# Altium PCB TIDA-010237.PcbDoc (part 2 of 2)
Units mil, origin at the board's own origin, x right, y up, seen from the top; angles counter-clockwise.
Board outline 2362.2 x 3346.46 mil, 4 copper layers (Top Layer, GND, Power, Bottom Layer), stack 61.6 mil thick; 143 components, 71 nets, 356 pads, 186 vias.
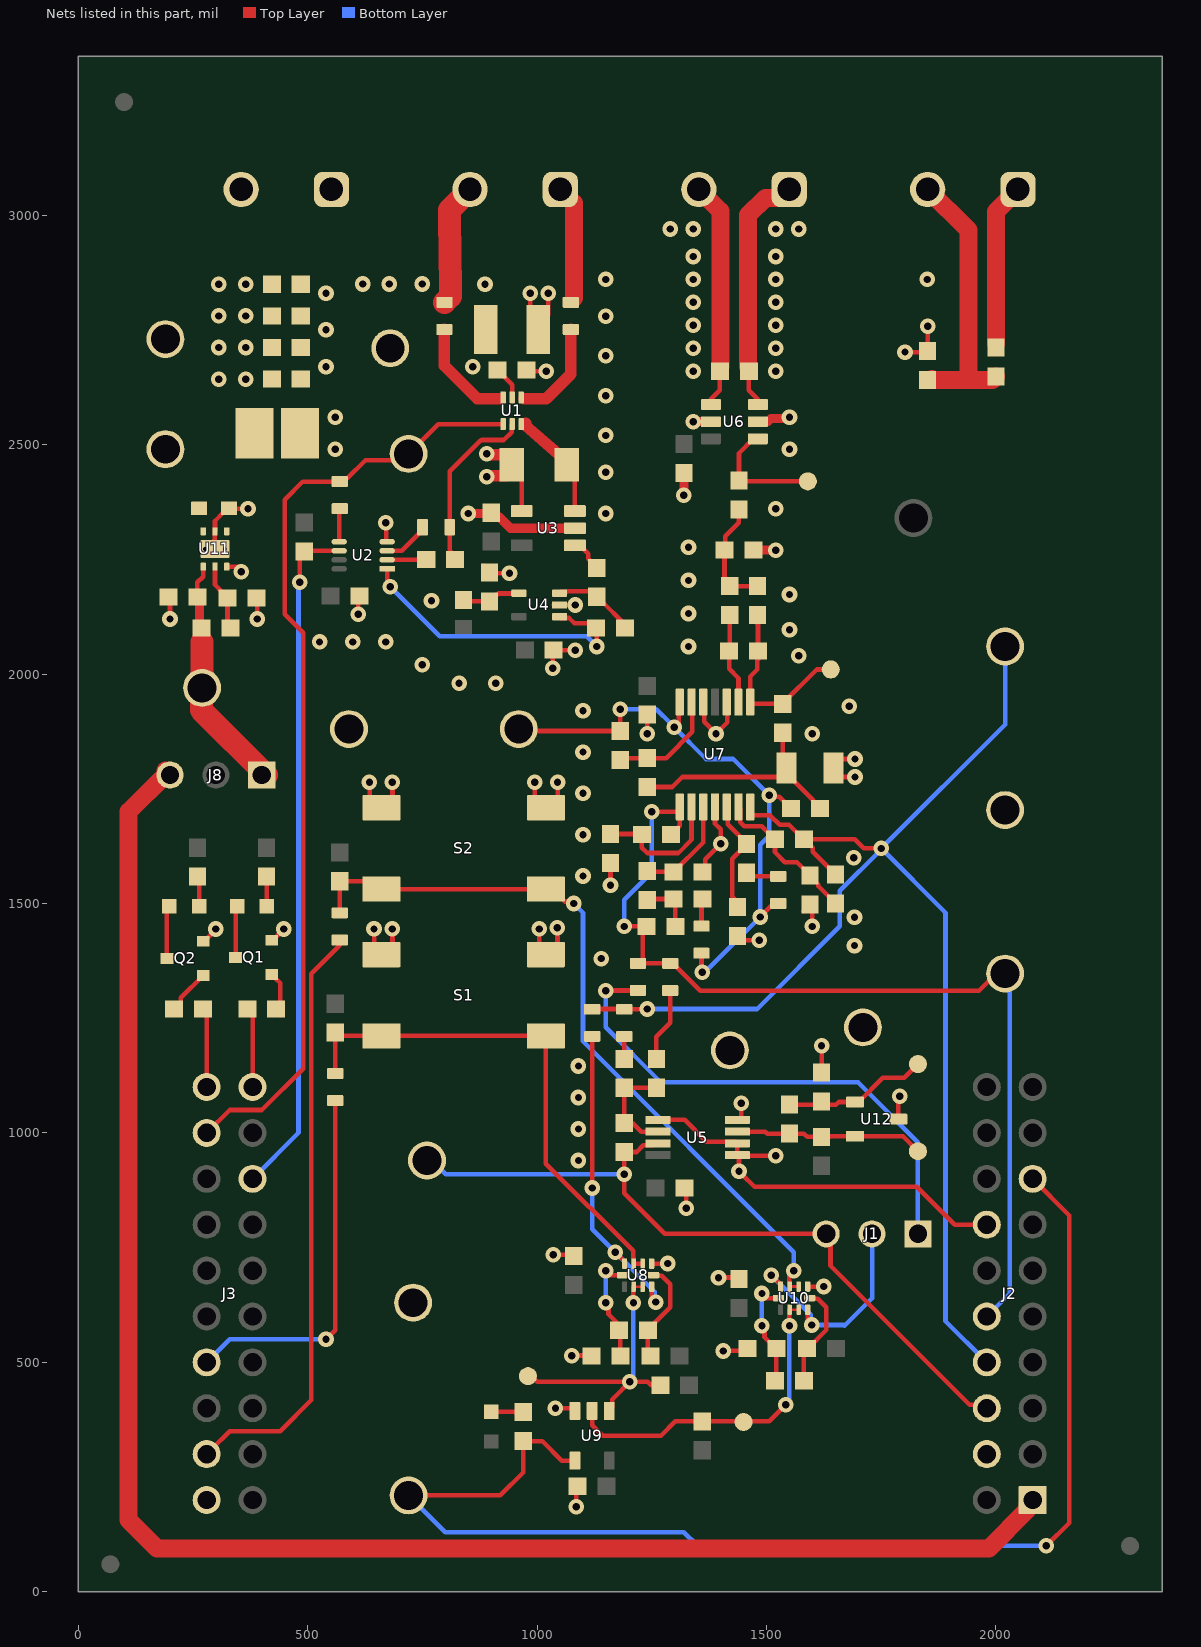
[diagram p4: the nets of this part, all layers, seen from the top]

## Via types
v1: diameter 34, hole 16, Top Layer to Bottom Layer, tented both sides, 184 vias
v2: diameter 19.68, hole 7.87, Top Layer to Bottom Layer, 2 vias

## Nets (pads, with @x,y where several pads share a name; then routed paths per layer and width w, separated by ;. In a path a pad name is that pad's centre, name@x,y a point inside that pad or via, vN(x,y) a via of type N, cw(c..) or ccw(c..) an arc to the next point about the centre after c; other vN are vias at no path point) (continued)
3V3-Launchpad: J2.1 J8.3 | length 3707.6
  Top Layer w39.37: J8.3@190,1790 190,1780 110,1700 110,156.81 172.13,94.68 1984.92,94.68 2069.17,178.94 2069.17,189.17 2076.85,196.85 J2.1@2077.24,196.85
3V3-LDO: C22.1 J8.1 R54.2 TP22.1 U11.1 | length 491.7
  Top Layer w10: C22.1@259.77,2167.98 259.77,2199.77 272.44,2212.44 U11.1@272.44,2234.21
  Top Layer w20: C22.1@259.77,2167.98 264.14,2163.62 264.14,2104.36 R54.2@268.5,2100
  Top Layer w50: 270,2070 268.5,1921.5 J8.1@410,1780
+12V: C1.1 C2.1 C21.2 C23.1 C24.1 C25.1 C26.1 C27.1 J4.2 TP12.1 U1.5 U11.4 U11.6 | length 63.2
  Top Layer w10: C2.1@914.17,2662.36 915.16,2662.36 928.86,2648.66 928.86,2647.68 945.67,2630.87 U1.5@945.67,2612.76
  other v1: 305.91,2642.68 364.96,2642.68 860,2670 305.91,2711.57 364.96,2711.57 305.91,2780.47 364.96,2780.47 305.91,2849.37 364.96,2849.37 886.61,2849.37
AC_clr: R34.2 R36.2 S1.1 S1.2 U8.2 U8.3 | length 1145.4
  Top Layer w10: R36.2@560,1129.53 R34.2@560,1218.5 ; R34.2@560.73,1218.5 567.81,1211.42 S1.2@660.87,1211.42 S1.1@1019.13,1211.42 1019.13,933.11 1209.25,743 1209.25,727.32 1210.16,726.42 U8.3@1210.16,715.1 U8.2@1229.84,715.1
AC_Sense+: J5.1 R15.2 U6.3 | length 523.3
  Top Layer w10: R15.2@1461.5,2660 1461.5,2618.9 1481.18,2599.21 U6.3@1481.18,2587.4
  Top Layer w39.37: R15.2@1460,2670 1460,3000 1497.55,3037.55 1530.83,3037.55 J5.1@1549.34,3056.06
AC_Sense-: J5.2 R15.1 U6.4 | length 486.5
  Top Layer w10: U6.4@1378.82,2587.4 1378.82,2599.21 1398.5,2618.9 R15.1@1398.5,2660
  Top Layer w39.37: J5.2@1352.49,3056.06 1400,3008.56 R15.1@1400,2670
AC_SENSING: C11.2 J2.24 R29.2 R32.2 R33.2 TP6.1 U7.14 | length 3025.4
  Top Layer w10: R29.2@1120,1270 1189.53,1270 R33.2@1190,1269.53 1239.53,1269.53 v1(1240,1270) ; U7.14@1464.57,1710.63 1464.57,1696.49 1468.43,1692.63 1507.37,1692.63 1528.43,1671.57 1548.94,1671.57 1580.51,1640 R32.2@1581.5,1640 R32.2@1582.48,1640 ; C11.2@1650,1562.99 1650,1563.98 1601.18,1612.8 1601.18,1621.3 R32.2@1582.48,1640 ; v1(1750,1620) 1712.25,1620 1692.25,1640 R32.2@1582.48,1640
  Bottom Layer w10: v1(1240,1270) 1479.75,1270 1660,1450.25 1660,1527.75 1750,1617.75 v1(1750,1620) ; J2.24@1980,500 1890,590 1890,1480 v1(1750,1620) ; TP6.1@2020,2060 2020,1890 v1(1750,1620)
AC_windowComp_CLR: J3.17 R36.1 | length 805.3
  Top Layer w10: v1(540,550) 560,570 R36.1@560,1070.47
  Bottom Layer w10: J3.17@280,510 290,510 330,550 v1(540,550)
COMPOSITE_SENSING: J1.3 J2.23 R40.2 TP8.1 U5.7 | length 1646.8
  Top Layer w10: U5.7@1260,980 1253.35,973.35 1231.64,973.35 1216.79,958.5 R40.2@1190,958.5 v1(1190,910) 1190,868.56 1278.56,780 J1.3@1630,780 1639.39,770.61 1639.39,710.61 1942.82,407.18 1972.82,407.18 J2.23@1980,400
  Bottom Layer w10: TP8.1@736.8,923.2 788.19,923.2 801.39,910 v1(1190,910)
DC_clr: R42.2 R46.2 S2.1 S2.2 U10.2 U10.3 | length 1649.3
  Top Layer w6: U10.3@1550.16,665.1 U10.2@1569.84,665.1
  Top Layer w10: R46.2@570,1479.53 R42.2@570,1548.5 S2.2@660.87,1548.5 ; S2.2@660.87,1531.42 S2.1@1019.13,1531.42 1032.91,1531.42 1059.91,1504.42 1075.58,1504.42 v1(1080,1500) ; U10.3@1550.16,665.1 1550.16,676.42 1550,676.57 1550,690 1559.65,699.65 v1(1559.65,700)
  Bottom Layer w10: v1(1080,1500) 1100,1480 1100,1200 1559.65,740.35 v1(1559.65,700)
DC_SENSING: C16.2 J2.25 R41.1 R47.2 R50.2 TP10.1 U7.8 | length 2172.1
  Top Layer w10: v1(1190,1450) C16.2@1238.5,1450 1230,1441.5 R50.2@1230,1369.53 ; R50.2@1220,1369.53 R50.2@1230,1369.53 ; v1(1250,1700) 1309.13,1700 1311.02,1701.89 1311.02,1714.57 1311.02,1669.56 1306.18,1664.72 1306.18,1663.7 1292.48,1650 R47.2@1290.51,1650 ; TP10.1@2020,1350 2003.17,1350 1963.17,1310 1355.43,1310 1295.91,1369.53 R41.1@1290,1369.53 R50.2@1230,1369.53
  Bottom Layer w10: v1(1190,1450) 1190,1507.75 1250,1567.75 v1(1250,1700) ; J2.25@1980,600 2030,650 2030,1340 TP10.1@2020,1350
DC_windowComp_CLR: J3.19 R46.1 | length 1300.9
  Top Layer w10: J3.19@280,310 290,310 330,350 440,350 507.87,417.87 507.87,1346.54 570,1408.66 R46.1@570,1420.47
FluxGate+: J6.2 R1.1 | length 269.8
  Top Layer w50: R1.1@798.03,2810 811,2823.27 811,2843.59 811,2843.88 810.99,2844.07 ccw(c761,2843.59) 810.99,2844.27 809.3,2990.56 809.3,3011.56 J6.2@853.81,3056.06
FluxGate-: J6.1 R2.1 | length 248.2
  Top Layer w39.37: J6.1@1050.66,3056.06 1080,3026.72 R2.1@1080,2820
GND: C1.2 C2.2 C3.2 C4.2 C5.2 C7.2 C8.2 C10.2 C12.2 C13.2 C14.2 C17.2 C18.2 C19.2 C21.1 C22.2 C23.2 C24.2 C25.2 C26.2 C27.2 J2.22 J3.20 J4.1 Q1.2 Q2.2 R3.1 R9.1 R19.1 R35.2 R53.2 R55.1 R57.1 S1.3 S1.4 S2.3 S2.4 TP13.1 TP14.1 TP15.1 TP16.1 TP17.1 TP19.1 U2.4 U3.2 U3.4 U4.2 U5.4 U6.2 U7.11 U8.1 U9.3 U10.1 U11.3 U11.5 U11.7@298.03,2272.6 U12.3 | length 2515.3
  Top Layer w10: v1(200,2120) C22.2@200,2161.36 ; Q2.2@272.36,1424.65 280.86,1424.65 299.92,1443.7 v1(299.92,1444.33) ; 296.06,2292.28 297.13,2293.35 297.13,2310.08 U11.5@298.03,2310.98 298.03,2333.62 315.59,2351.18 316.06,2351.18 325.59,2360.71 C21.1@325.59,2361.18 ; U11.3@323.51,2234.1 323.88,2233.72 354.63,2233.72 v1@355.12,2233.23 ; C21.1@326.88,2361.18 327.47,2360.59 369.41,2360.59 v1(370,2360) ; R55.1@388.3,2166.03 390,2164.32 v1(390,2120) ; Q1.2@425.49,1422.26 Q1.2@427.87,1424.65 ; Q1.2@428.5,1424.65 v1@447.56,1443.7 ; v1(610,2130) C5.2@610,2167.24 ; S2.4@634.9,1729.53 v1@634.9,1764.29 ; S1.4@644.9,1409.53 v1@644.9,1444.29 ; v1(670,2330) 671.53,2328.47 671.53,2289.12 672.31,2288.35 U2.4@673.07,2288.35 ; S1.4@684.9,1409.53 v1@684.9,1444.29 ; S2.4@684.9,1729.53 v1@684.9,1764.29 ; R9.1@883.17,2235.69 898.86,2220 v1(940,2220) ; R3.1@944.64,2445.83 966.34,2424.13 966.34,2360.19 U3.4@955.51,2349.37 ; C2.2@978.14,2662.36 980.5,2660 v1(1020,2660) ; C1.2@985.04,2782.44 v1(985.04,2829.69) ; S2.3@994.9,1729.53 v1@994.9,1764.29 ; C1.2@1002.76,2750.94 C1.2@1017.84,2735.86 ; S1.3@1004.9,1409.53 v1@1004.9,1444.29 ; C1.2@1024.41,2782.44 v1(1024.41,2829.69) ; v1(1034.25,2012.76) C4.2@1034.25,2060 ; v1(1035.47,734.67) 1035.71,734.9 C14.2@1070.47,734.9 ; C4.2@1036.22,2052.13 v1(1083.46,2052.13) ; U4.2@1036.22,2150.55 v1(1083.46,2150.55) ; v1(1040,400) 1084.43,400 U9.3@1084.9,399.53 ; S1.3@1044.49,1412.5 v1@1044.49,1447.26 ; S2.3@1044.9,1729.53 v1@1044.9,1764.29 ; v1(1075.47,514.67) 1075.71,514.9 R35.2@1110.47,514.9 ; C18.2@1085.1,220.47 1085.1,185.71 v1(1085.33,185.47) ; v1(1240,1870) 1240,1903.39 1250,1913.39 C10.2@1250,1921.26 ; U8.1@1249.53,715.1 1284.29,715.1 v1(1284.53,715.33) ; C7.2@1325.1,870.47 1325.1,835.71 v1(1325.33,835.47) ; C19.2@1360.24,1568.9 1366.74,1575.4 1366.74,1596.74 v1(1400,1630) 1399.93,1630.07 1399.93,1662 1387.8,1674.13 U7.11@1387.8,1714.57 ; v1(1395.47,684.67) 1395.71,684.9 C17.2@1430.47,684.9 ; v1(1405.47,524.67) 1405.71,524.9 R53.2@1440.47,524.9 ; v1@1440,1060 1441.18,1061.18 1444.9,1061.18 U5.4@1444.9,1029.53 ; U10.1@1589.53,665.1 1624.29,665.1 v1(1624.53,665.33) ; R19.1@1620,1131.5 v1(1620,1190) ; C13.2@1653.54,1783.46 1661.42,1775.59 v1(1692.91,1775.59) ; C13.2@1661.42,1814.96 v1(1692.91,1814.96) ; U12.3@1787.24,1030 1787.24,1067.24 1790,1070 v1(1790,1080) ; v1(1801.81,2701.73) R57.1@1849.05,2701.73 ; R57.1@1851.73,2710.94 v1(1851.73,2758.19)
  Top Layer w19.68: v1(1320,2390) C8.2@1320,2438.5 ; C12.2@1471.5,2270 v1(1520,2270) ; U6.2@1481.18,2550 1502.83,2550 1510.1,2557.26 1547.26,2557.26 v1(1550,2560)
  Top Layer w20: v1@860,2350 C3.2@900,2350 ; C3.2@900,2351.5 900,2350.51 908.7,2341.81 918.19,2341.81 942.13,2317.87 U3.2@1082.48,2317.87
  Top Layer w25: v1(890,2430) 891.72,2431.72 931.72,2431.72 R3.1@938.28,2438.28 ; v1@891.72,2478.28 R3.1@938.28,2478.28 ; R3.1@938.28,2458.28 R3.1@940,2460
  other v1: 1090.12,940 1090.12,1008.59 1444.67,1064.53 1090.12,1077.19 1090.12,1145.78 1140,1380 1691.81,1408.33 447.56,1444.33 644.67,1444.53 684.67,1444.53 1004.67,1444.53 1044.25,1447.5 1691.81,1470 1100,1560 1690,1600 1100,1650 1100,1740 634.67,1764.53 684.67,1764.53 994.67,1764.53 1044.67,1764.53 1100,1830 1600,1870 1100,1920 1680,1930 830,1980 910,1980 750,2020 1570,2040 1330,2060 525.96,2070 597.98,2070 670,2070 1550,2096.67 1330,2132.02 770,2160 1550,2173.33 1330,2204.04 355.12,2223.23 1330,2276.06 850,2350 1150,2350 1520,2360 1150,2440 890,2480 560,2490 1550,2490 1150,2520 560,2560 1150,2606.67 1340,2660 1520,2660 540,2670 1150,2693.33 1340,2710 1520,2710 540,2750 1340,2760 1520,2760 1150,2780 1340,2810 1520,2810 540,2830 620,2850 677.98,2850 750,2850 1150,2860 1340,2860 1520,2860 1850,2860 1340,2910 1520,2910 1290,2970 1340,2970 1520,2970 1570,2970
  other v2: 276.38,2272.6 319.68,2272.6
GREEN_LED: J3.11 R60.2 | length 170
  Top Layer w10: J3.11@280,1100 R60.2@280,1270
I_fault: C9.1 R13.2 R28.2 R48.2 TP3.1 U7.7 | length 1314.5
  Top Layer w10: TP3.1@960,1880 964.02,1875.98 C9.1@1181.1,1875.98 v1(1181.1,1923.23) ; v1@1309.13,1893.78 U7.7@1309.13,1933.15 ; R48.2@1358.27,1391.73 1358.27,1351.73 v1(1360,1350) ; v1@1486.22,1471.1 R28.2@1520.36,1505.23 ; v1(1505.91,1736.22) 1509.67,1732.45 1527.39,1732.45 1538.46,1721.38 1538.46,1720.39 1552.17,1706.69 R13.2@1553.15,1706.69
  Bottom Layer w10: v1(1181.1,1923.23) 1259.84,1923.23 1293.07,1890 v1@1300,1890 ; v1@1296.54,1886.54 v1(1299.21,1883.86) 1368.11,1814.96 1427.17,1814.96 v1(1505.91,1736.22) 1505.91,1647.64 1486.22,1627.95 v1(1486.22,1470.47) 1365.75,1350 v1(1360,1350)
NetC6_1: C6.1 R12.2 R21.1 TP2.1 U7.1 | length 408.2
  Top Layer w10: R12.2@1480,2128.5 1480,2108.82 1481.5,2107.32 C6.1@1481.5,2050 1481.5,2031.3 1480,2029.8 1480,2010 1464.57,1994.57 U7.1@1464.57,1938.98 1464.57,1935.04 1471.46,1935.04 R21.1@1535.43,1935.04 1535.43,1936.02 1609.41,2010 TP2.1@1640,2010
NetC6_2: C6.2 R16.2 U7.2 | length 198.6
  Top Layer w10: R16.2@1420,2128.5 1420,2051.5 C6.2@1418.5,2050 1418.5,2011.5 1438.98,1991.02 U7.2@1438.98,1938.98
NetC9_2: C9.2 R22.2 U7.6 | length 241
  Top Layer w10: C9.2@1181.1,1814.96 1183.07,1816.93 1281.5,1816.93 1338.58,1874.02 U7.6@1338.58,1933.07
NetC11_1: C11.1 R31.2 R32.1 U7.13 | length 336.3
  Top Layer w10: U7.13@1438.98,1710.63 1442.83,1706.77 1442.83,1676.91 1451.52,1668.23 1489.29,1668.23 1503.82,1653.7 1517.52,1640 R32.1@1518.5,1640 1518.5,1611.5 1540,1590 1566.5,1590 1594.49,1562.01 R31.2@1594.49,1561.02 1594.49,1560.04 1613.19,1541.34 1613.19,1537.8 1650,1500.98 C11.1@1650,1500
NetC12_1: C12.1 R12.1 R16.1 R18.2 | length 244.6
  Top Layer w10: C12.1@1408.5,2270 1408.5,2212.68 1410,2211.18 1410,2191.5 R12.1@1480,2191.5 ; C12.1@1410,2275.44 1410,2300 1439.68,2329.68 1439.68,2358.18 R18.2@1440,2358.5
NetC13_1: C13.1 R13.1 R21.2 R22.1 | length 455
  Top Layer w10: R22.1@1240.16,1753.94 1294.97,1753.94 1316.62,1775.59 C13.1@1525.59,1775.59 ; C13.1@1535.43,1795.28 R21.2@1535.43,1872.05 ; C13.1@1555.12,1771.59 1601.46,1725.25 1601.46,1714.98 R13.1@1607.12,1709.31
NetC15_1: C15.1 R27.1 U7.12 | length 264.4
  Top Layer w10: U7.12@1413.39,1714.57 1415.28,1712.68 1415.28,1672.32 1456.69,1630.91 1456.69,1628.94 1425.12,1597.36 1425.12,1514.84 1446.85,1493.11 R27.1@1446.85,1492.13 ; R27.1@1437.01,1490.16 R27.1@1437.01,1492.13
NetC15_2: C15.2 R28.1 | length 72.2
  Top Layer w10: C15.2@1456.69,1566.93 1464.57,1559.06 R28.1@1525.59,1559.06
NetC16_1: C16.1 R45.1 R49.2 | length 115.8
  Top Layer w10: R45.1@1240,1510 1240.16,1509.84 R49.2@1297.24,1509.84 ; C16.1@1301.5,1450 R49.2@1301.5,1508.5
NetC19_1: C19.1 R45.2 U7.10 | length 230.2
  Top Layer w10: R45.2@1240.16,1568.9 C19.1@1297.24,1568.9 1298.23,1568.9 1362.2,1632.87 U7.10@1362.2,1714.57
NetD1_1: D1.1 R38.2 | length 70.4
  Top Layer w10: D1.1@900,392.48 950.31,392.48 951.3,391.5 R38.2@970,391.5
NetD4_1: D4.1 Q2.3 | length 115.2
  Top Layer w10: Q2.3@193.39,1380.48 193.39,1488.39 D4.1@198.54,1493.54
NetD4_2: D4.2 R59.1 | length 66.4
  Top Layer w10: R59.1@260,1558.5 263.5,1555 D4.2@263.5,1493.54
NetD5_1: D5.1 Q1.3 | length 112.4
  Top Layer w10: Q1.3@342.89,1382.48 342.89,1490.25 D5.1@346.18,1493.54
NetD5_2: D5.2 R58.1 | length 80
  Top Layer w10: R58.1@408.19,1572.28 411.14,1569.33 D5.2@411.14,1493.54
NetJ1_1: J1.1 R50.1 | length 1133.7
  Top Layer w10: v1(1150,1310) 1150.47,1310.47 R50.1@1220,1310.47
  Bottom Layer w10: v1(1150,1310) 1150,1230 1270,1110 1700,1110 1830,980 J1.1@1830,780
NetJ1_2: J1.2 U10.4 U10.9 | length 512.8
  Top Layer w10: v1(1510,690) 1510.98,690 1530.47,670.51 U10.4@1530.47,665.1 ; U10.9@1589.53,614.9 1589.53,603.58 1590,603.11 1590,590 v1(1598.62,581.38)
  Bottom Layer w10: v1(1510,690) 1595.99,604.01 1595.99,584.01 v1(1598.62,581.38) 1670,581.38 ; 1670,580 1730,640 J1.2@1730,780
NetQ1_1: Q1.1 R61.2 | length 97.1
  Top Layer w10: Q1.1@421.63,1345.08 423.6,1345.08 430.41,1338.27 430.41,1336.3 440,1326.71 R61.2@440,1256.79
NetQ2_1: Q2.1 R60.1 | length 100.8
  Top Layer w10: R60.1@220,1263.86 223.7,1267.57 223.7,1294.65 Q2.1@272.13,1343.08
NetR1_2: R1.2 U1.6 | length 230.1
  Top Layer w25: R1.2@798.03,2750.94 798.03,2671.97 870,2600 919.39,2600
NetR2_2: R2.2 U1.4 | length 221.2
  Top Layer w25: 971.95,2600 1020,2600 1073.62,2653.62 R2.2@1073.62,2750.94
NetR5_2: R5.2 U2.5 | length 71.8
  Top Layer w10: R5.2@561.85,2357.24 568.66,2350.43 U2.5@568.66,2288.35
NetR6_2: R6.2 U2.3 | length 99.3
  Top Layer w10: U2.3@673.07,2268.66 673.39,2268.98 705.36,2268.98 748.82,2312.44 R6.2@748.82,2317.87
NetR7_2: R7.2 U2.2 | length 65.9
  Top Layer w10: U2.2@673.07,2248.98 R7.2@738.98,2248.98
NetR8_1: R8.1 U3.1 | length 75
  Top Layer w10: U3.1@1082.48,2280.47 1093.31,2280.47 1111.3,2262.48 1111.3,2251.18 1130,2232.48 R8.1@1130,2231.5
NetR8_2: R8.2 R11.1 U4.3 | length 186.1
  Top Layer w10: U4.3@1049.02,2176.14 1051.89,2179.02 1065.2,2179.02 1066.61,2180.43 1099.38,2180.43 1099.47,2180.33 1118.17,2180.33 R8.2@1130,2168.5 1130,2167.52 1143.7,2153.82 1145.87,2153.82 1184.45,2115.24 1184.45,2114.25 1198.15,2100.55 R11.1@1199.13,2100.55
NetR11_2: R11.2 U2.1 U4.1 | length 663
  Top Layer w10: U2.1@673.07,2229.29 673.07,2203.27 679.92,2196.42 v1(679.92,2189.92) ; U4.1@1049.02,2124.96 1051.89,2122.09 1069.68,2122.09 1081.44,2110.32 1119.68,2110.32 R11.2@1120,2110 ; R11.2@1128.5,2099.06 1130,2097.56 v1(1130,2060)
  Bottom Layer w10: v1(679.92,2189.92) 787.84,2082 1108,2082 v1(1130,2060)
NetR14_2: R14.2 R17.2 TP20.1 U5.3 U12.2 | length 412
  Top Layer w10: U5.3@1436.61,1002.8 1497.2,1002.8 1501.5,998.5 1581.5,998.5 1588.5,991.5 1638.7,991.5 1639.8,992.6 U12.2@1692.76,992.6 1797.4,992.6 TP20.1@1830,960
NetR17_1: R17.1 R19.2 TP21.1 U12.1 | length 316.7
  Top Layer w10: R17.1@1550,1061.5 1651.5,1061.5 1657.4,1067.4 U12.1@1692.76,1067.4 1700.63,1067.4 1753.23,1120 1800,1120 TP21.1@1830,1150
NetR18_1: R18.1 TP5.1 U6.1 | length 258.1
  Top Layer w10: R18.1@1440,2421.5 1440,2481.26 1471.34,2512.6 U6.1@1481.18,2512.6 ; R18.1@1445.86,2420 TP5.1@1590,2420
NetR25_2: R25.2 TP7.1 U8.7 U8.8 U9.1 | length 609.3
  Top Layer w6: U8.7@1210.16,664.9 U8.8@1229.84,664.9
  Top Layer w10: TP7.1@980,470 987.92,470 1000.54,457.38 1197.38,457.38 v1@1200,460 ; U9.1@1157.4,394.13 1163.92,400.65 1163.92,419.15 1168.62,423.85 v1(1202.15,457.38) ; v1@1202.62,457.38 1241.44,457.38 1248.82,450 R25.2@1268.5,450 ; v1(1210,630) 1210,653.43 1210.16,653.58 U8.7@1210.16,664.9
  Bottom Layer w10: v1(1202.15,457.38) 1200,459.53 1200,460 1210,470 v1(1210,630)
NetR26_2: R26.2 R30.2 U8.10 | length 225.1
  Top Layer w10: R26.2@1241.5,510 1241.5,572.99 1248.5,580 1249.49,580 1290,620.51 1290,670 1271.6,688.4 1261.26,688.4 1259.66,690 U8.10@1253.86,690
NetR29_1: R29.1 U8.4 U8.9 | length 707.8
  Top Layer w10: v1(1120,880) R29.1@1120,1210.47 ; v1(1170,740) 1170.98,740 1190.47,720.51 U8.4@1190.47,715.1 ; U8.9@1249.53,664.9 1249.53,653.58 1250,653.11 1250,640 v1(1258.62,631.38)
  Bottom Layer w10: v1(1120,880) 1120,790 v1(1170,740) 1255.99,654.01 1255.99,634.01 v1(1258.62,631.38)
NetR30_1: R30.1 R35.1 U8.5 | length 245.1
  Top Layer w10: v1(1150,630) 1155.6,624.4 1155.6,604.92 1180.51,580 1181.5,580 1181.5,512.99 R35.1@1178.5,510 ; v1(1150,700) 1160,690 U8.5@1186.14,690
  Bottom Layer w10: v1(1150,630) v1(1150,700)
NetR33_1: R33.1 R37.1 | length 49
  Top Layer w10: R37.1@1190,1161.5 R33.1@1190,1210.47
NetR37_2: R37.2 R39.2 R40.1 U5.6 | length 228.1
  Top Layer w10: R39.2@1260,1098.5 R37.2@1190,1098.5 R40.1@1190,1021.5 1208.7,1021.5 1227.4,1002.8 U5.6@1263.39,1002.8
NetR39_1: R39.1 R41.2 | length 161.4
  Top Layer w10: R39.1@1260,1161.5 1260,1210 1290,1240 R41.2@1290,1310.47
NetR43_2: R43.2 TP11.1 U9.2 U10.7 U10.8 | length 722.8
  Top Layer w6: U10.7@1550.16,614.9 U10.8@1569.84,614.9
  Top Layer w10: U9.2@1120,394.13 1120,363.33 1143.33,340 1270,340 1301.5,371.5 R43.2@1360,371.5 1460,371.5 1506.27,371.5 v1(1542.15,407.38) ; v1(1550,580) 1550,603.43 1550.16,603.58 U10.7@1550.16,614.9
  Bottom Layer w10: v1(1542.15,407.38) 1540,409.53 1540,410 1550,420 v1(1550,580)
NetR44_2: R44.2 R51.2 U10.10 | length 225.1
  Top Layer w10: R51.2@1581.5,460 1581.5,522.99 R44.2@1588.5,530 1589.49,530 1630,570.51 1630,620 1611.6,638.4 1601.26,638.4 1599.66,640 U10.10@1593.86,640
NetR47_1: R47.1 R52.2 U7.9 | length 298.4
  Top Layer w10: R52.2@1160,1651.5 1227.01,1651.5 R47.1@1228.5,1650 1228.5,1621.5 1240,1610 1308.09,1610 1336.61,1638.53 U7.9@1336.61,1714.57
NetR48_1: R48.1 R49.1 | length 59.9
  Top Layer w10: R48.1@1358.27,1450.79 1358.27,1507.87 R49.1@1360.24,1509.84
NetR51_1: R51.1 R53.1 U10.5 | length 245.1
  Top Layer w10: v1(1490,580) 1495.6,574.4 1495.6,554.92 1520.51,530 R53.1@1521.5,530 1521.5,462.99 R51.1@1518.5,460 ; v1(1490,650) 1500,640 U10.5@1526.14,640
  Bottom Layer w10: v1(1490,580) v1(1490,650)
NetR54_1: R54.1 R55.2 U11.2 | length 108.9
  Top Layer w10: 298.03,2224.21 298.03,2194.32 R55.2@313.78,2178.57 ; R54.1@325.3,2109.28 R55.2@325.3,2166.03
nFault: J2.8 R38.1 TP9.1 U9.4 | length 2802.1
  Top Layer w10: TP9.1@695.92,210 920,210 970,260 R38.1@970,328.5 1011.5,328.5 1054.13,285.87 U9.4@1082.6,285.87 ; J2.8@2080,900 2160,820 2160,150 v1(2110,100)
  Bottom Layer w10: TP9.1@706.47,223.53 800,130 1320,130 1350,100 v1(2110,100)
Pulse+: J3.12 R5.1 TP1.1 U1.1 | length 2096.6
  Top Layer w10: J3.12@280,1000 330,1050 400,1050 490,1140 490,2090 450,2130 450,2380 489.53,2419.53 R5.1@570,2419.53 576.81,2426.34 586.34,2426.34 626.09,2466.09 706.09,2466.09 784.65,2544.65 U1.1@925.98,2544.65
  Bottom Layer w10: TP1.1@720,2489.84 TP1.1@739.68,2470.16
Pulse-: R6.1 R7.1 U1.2 | length 393.1
  Top Layer w10: R6.1@809.53,2320 809.53,2441.78 877.63,2509.87 879.87,2509.87 880,2510 927.5,2510 944.76,2527.27 944.76,2534.65 944.76,2543.74 945.67,2534.65 U1.2@945.67,2544.49 ; R6.1@810,2320 810,2268.5 R7.1@819.69,2258.82
RED_LED: J3.31 R61.1 | length 153.8
  Top Layer w10: J3.31@380,1100 R61.1@380,1253.81
RESET_n: J3.33 R10.2 U2.6 | length 1503.2
  Top Layer w10: v1(483.07,2199.76) 483.07,2257.17 494.57,2268.66 U2.6@571.65,2268.66
  Bottom Layer w10: J3.33@370,900 J3.33@380,900 480.13,1000.13 480.13,2196.82 v1(483.07,2199.76)
Test+: J7.1 R56.2 | length 356
  Top Layer w39.37: R56.2@2000,2720 2000,3008.03 J7.1@2048.03,3056.06
Test-: J7.2 R56.1 R57.2 | length 595.1
  Top Layer w39.37: J7.2@1851.18,3056.06 1939.76,2967.48 1939.76,2640.71 ; R57.2@1861.02,2642.68 1862.99,2640.71 1939.76,2640.71 ; R56.1@2000,2648.5 1992.2,2640.71 1939.76,2640.71
Vmid: J2.27 R27.2 R31.1 R52.1 TP4.1 U5.1 U5.2 U5.5 U6.5 U7.3 U7.5 | length 1244.5
  Top Layer w10: v1(1160,1540) R52.1@1160,1588.5 ; U5.5@1263.39,1028.39 1321.61,1028.39 1368.94,981.06 1432.76,981.06 U5.2@1436.61,977.2 U5.1@1436.61,955.51 ; U7.5@1364.09,1933.15 1364.09,1895.91 v1(1390,1870) 1414.52,1894.52 1414.52,1906.34 ; U5.1@1436.61,951.61 U5.1@1440,951.61 ; v1@1440,910 1446.14,910 1473.74,882.4 1827.6,882.4 1910,800 J2.27@1980,800 ; v1(1440,916.14) U5.1@1440,951.61 ; U5.1@1440,955.51 U5.1@1440,951.61 ; R27.2@1444.49,1420 v1(1483.86,1420) ; v1(1520,950) 1441.61,950 U5.1@1440,951.61 ; R31.1@1579.8,1483.35 1580.79,1483.35 R31.1@1594.49,1497.05 ; R31.1@1594.49,1500 1600,1494.49 v1(1600,1450)
  Top Layer w19.68: v1(1340,2550) U6.5@1378.5,2550
VREF_695mV: R4.1 R9.2 U4.4 | length 126.3
  Top Layer w10: R4.1@841.57,2158.43 R9.2@896.46,2158.43 896.46,2159.41 910.16,2173.11 913.61,2173.11 916.02,2175.51 U4.4@960.25,2175.51
VSENSE: R3.2 U1.3 U3.3 | length 237
  Top Layer w10: R3.2@1069.21,2460.08 1082.48,2446.81 U3.3@1082.48,2355.28
  Top Layer w25: 974.84,2546.17 974.9,2545.31 975.18,2541.3 1046,2479.75 1060.25,2479.75 R3.2@1070,2470
pads on no net: FID1.1 FID2.1 FID3.1 J2.2 J2.3 J2.4 J2.5 J2.6 J2.7 J2.9 J2.10 J2.21 J2.26 J2.28 J2.29 J2.30 J3.13 J3.14 J3.15 J3.16 J3.18 J3.32 J3.34 J3.35 J3.36 J3.37 J3.38 J3.39 J3.40 U11.7@280.32,2272.6 U11.7@315.75,2272.6

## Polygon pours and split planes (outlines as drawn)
GND on GND "GND_GND_P045" (solid, remove dead copper, pour order 45): 269.92,3270 2080,3270 2300,3050 2300,190 2160,50 190,50 61.28,178.72 58.38,3058.25
Vmid on Power "POWER_VMID_P043" (solid, pour order 43): 1490,2570 1490,1900 1640,1750 1640,1070 1540,970 1540,940 1500,900 1390,900 1340,950 1340,1270 1130,1480 1130,1850 1320,2040 1320,2550 1340,2570
+12V on Power "POWER_+12V_P042" (solid, pour order 42): 955.51,2645.51 955.51,2844.49 921.1,2878.9 148.9,2878.9 99.21,2829.21 99.21,2650.79 156.54,2593.46 903.46,2593.46
3V3 on Power "POWER_3V3_P044" (solid, pour order 44): 269.89,3270 2080,3270 2300,3050 2300,190 2160,50 190,50 61.32,178.68 58.42,3058.32
GND on Top Layer "GND_Por_Bottom" (solid, remove dead copper, pour order 46): 150,0 2200,0 2362.2,162.2 2362.2,3077.8 2093.54,3346.46 276.46,3346.46 0,3070 0,150
3V3 on Top Layer "TOP_LAYER_3V3_P037" (solid, remove dead copper, pour order 37): 290,1810 340,1810 340,1760 370,1730 390,1730 430,1690 430,1600 240,1600 190,1650 190,1710
+12V on Top Layer "TOP_LAYER_+12V_P035" (solid, remove dead copper, pour order 35): 868.9,2878.9 921.1,2878.9 935.83,2864.17 935.83,2665.83 922.52,2652.52 857.48,2652.52 850,2660 850,2860
+12V on Top Layer "TOP_LAYER_+12V_P040" (solid, remove dead copper, pour order 40): 424.02,2160 424.02,2603.31 443.7,2622.99 443.7,3036.3 355.04,3124.96 144.96,3124.96 99.21,3079.21 99.21,2219.45 158.66,2160
GND on Bottom Layer "GND_Por_Bottom" (solid, remove dead copper, pour order 47): 170,-30 2220,-30 2362.2,112.2 2362.2,3067.8 2110,3320 250,3320 20,3090 20,120

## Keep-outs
Keep-Out Layer:
  text ".Layer_Name" at 577,-858.49 h60

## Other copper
Top Layer:
  text ".Layer_Name" at 577,-858.49 h60
Bottom Layer:
  text ".Layer_Name" at 577,-858.49 h60

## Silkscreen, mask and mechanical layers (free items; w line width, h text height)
Top Overlay:
  lines w10: 150,150 10,150 10,230 150,230 ; 180,150 220,190 180,230 ; 1740,270 1740,350 1880,350 1920,310 1880,270 1740,270 ; 2140,210 2180,250 2320,250 2320,170 2180,170 2140,210
  text "12V" at 250,3250 h59.06
  text "GND" at 530,3250 h59.06
  text "Flux Gate Driver" at 760,3250 h59.06
  text "Sense Coil" at 1320,3250 h59.06
  text "Test-" at 1770,3250 h59.06
  text "Test+" at 2010,3250 h59.06
  text "GND" at 620,2780 h59.06
  text "12V" at 150,2600 h59.06
  text "Pulse+" at 630,2560 h59.06
  text "3V3" at 1770,2450 h59.06
  text "GND" at 120,2320 h59.06
  text "AC Sense" at 1910,2160 h59.06
  text "GND" at 530,1960 h59.06
  text "3V3-LDO" at 410,1850 h59.06 r90
  text "3V3-LP" at 60,1840 h59.06
  text "GND" at 1960,1800 h59.06
  text "I Fault" at 730,1740 h66.93
  text "DC Clear" at 740,1450 h59.06
  text "DC Sense" at 1910,1440 h59.06
  text "GND" at 1660,1330 h59.06
  text "Vmid" at 1390,1280 h59.06
  text "AC Clear" at 740,1120 h59.06
  text "Comp." at 1580,840 h59.06
  text "Composite Sense" at 550,810 h59.06
  text "Out" at 1680,680 h59.06
  text "DC" at 1800,680 h59.06
  text "GND" at 670,490 h59.06
  text "GND" at 1768,288 h40
  text "Rev E3" at 180,280 h72.83 r90
  text "BOOSTXL-RCD" at 82,275 h100 r90
  text "3V3" at 2186.6,188.41 h40
  text "GND" at 38,168 h40
  text "nFault" at 640,80 h59.06
  text ".Layer_Name" at 577,-858.49 h60 r180
Bottom Overlay:
  text ".Layer_Name" at 577,-858.49 h60
Top Paste:
  text ".Layer_Name" at 577,-858.49 h60
Bottom Paste:
  text ".Layer_Name" at 577,-858.49 h60
Top Solder:
  text ".Layer_Name" at 577,-858.49 h60
  text ".Layer_Name" at 577,-858.49 h60
Bottom Solder:
  text ".Layer_Name" at 577,-858.49 h60
Drill Guide:
  text ".Layer_Name" at 577,-858.49 h60
M1 Board Outline:
  the board outline again, w10
  text ".Layer_Name" at 577,-858.49 h60
M2 Board Dimensions:
  rectangle: 0,-275 125,-150
  rectangle: 125,-400 500,-275
  lines w7: 0,-275 1000,-275 ; 125,-400 125,-150 ; 250,-400 250,-150 ; 500,-400 500,-150 ; 750,-400 750,-150 ; 0,-400 1000,-400 1000,-150 0,-150 0,-400
  text ".Layer_Name" at 577,-858.49 h60
M3 3D STEP Top:
  text ".Layer_Name" at 577,-858.49 h60
M4 3D STEP Bottom:
  text ".Layer_Name" at 577,-858.49 h60
M5 Assembly Top:
  lines w10: -292,-930.17 6308,-930.17 ; -292,-726.83 6310,-726.83 ; -292,-523.5 -292,-1133.5 3713,-1133.5 6310,-1133.5 6310,-523.5 -291.5,-523.5 -291.5,-1133.5 1284,-1133.5 ; 2173,-1133.5 2173,-523.5 ; 3440,-726.83 3440,-523.5 ; 4280,-726.83 4280,-523.5 ; 4902,-1140 4902,-937.17
  text "COMPONENTS MARKED 'DNP' SHOULD NOT BE POPULATED." at 1153.5,-318.5 h60
  text "ASSEMBLY VARIANT:" at 1153,-434 h60
  text ".VariantName" at 2189,-434 h60
  text "PCB VIEWED FROM TOP SIDE" at -228.5,-655.67 h60
  text "BOARD #:" at 2248,-655.67 h60
  text ".PRJ_Number" at 2793.5,-655.67 h60
  text "REV:" at 3638,-655.67 h60
  text ".PCB_Rev" at 3929.5,-655.67 h60
  text "SVN REV:" at 4476,-655.67 h60
  text ".VersionControl_RevNumber" at 4982,-655.67 h60
  text "TID #:" at 2248,-859 h60
  text ".TID" at 2793.5,-859 h60
  text "PLOT NAME =" at -228.5,-1064.34 h60
  text ".plot_File_Name" at 577,-1064.34 h60
  text "GENERATED    :" at 2250,-1064.34 h60
  text ".Print_Date" at 3119.5,-1064.34 h60
  text ".Print_Time" at 3848.5,-1064.34 h60
  text "TEXAS INSTRUMENTS" at 5113,-1064.34 h60
M6 Assembly Bottom:
  lines w10: -292.5,-727.33 6309.5,-727.33 ; -290.5,-930.67 6309.5,-930.67 ; 1115.5,-1140.5 1115.5,-937.67 ; 1737.5,-727.33 1737.5,-524 ; 2577.5,-727.33 2577.5,-524 ; 3844.5,-1134 3844.5,-524 ; 4733.5,-1134 6309,-1134 6309,-524 -292.5,-524 -292.5,-1134 2304.5,-1134 6309.5,-1134 6309.5,-524
  text "COMPONENTS MARKED 'DNP' SHOULD NOT BE POPULATED." at 6102,-318 h60
  text ".VariantName" at 5058,-434 h60
  text "ASSEMBLY VARIANT:" at 6097,-434 h60
  text ".VersionControl_RevNumber" at 1035.5,-656.17 h60
  text "SVN REV:" at 1541.5,-656.17 h60
  text ".PCB_Rev" at 2088,-656.17 h60
  text "REV:" at 2379.5,-656.17 h60
  text ".PRJ_Number" at 3224,-656.17 h60
  text "BOARD #:" at 3769.5,-656.17 h60
  text "PCB VIEWED FROM BOTTOM SIDE" at 6246,-656.17 h60
  text ".TID" at 3224,-859.5 h60
  text "TID #:" at 3769.5,-859.5 h60
  text "TEXAS INSTRUMENTS" at 904.5,-1064.84 h60
  text ".Print_Time" at 2169,-1064.84 h60
  text ".Print_Date" at 2898,-1064.84 h60
  text "GENERATED    :" at 3767.5,-1064.84 h60
  text ".plot_File_Name" at 5440.5,-1064.84 h60
  text "PLOT NAME =" at 6246,-1064.84 h60
M9 Title Sheet:
  drawing of 57 lines, arcs and shapes, not listed
  text "1" at 739.84,8036.5 h70
  text "2" at 3235.5,8036.5 h70
  text "3" at 5724.84,8036.5 h70
  text "4" at 8231.51,8036.5 h70
  text "5" at 10730.5,8036.5 h70
  text "6" at 13235.5,8036.5 h70
  text "A" at -416.5,6893.5 h70
  text "A" at 14383.5,6893.5 h70
  text "B" at -416.5,4513.5 h70
  text "B" at 14383.5,4513.5 h70
  text "C" at -416.5,2138.5 h70
  text "C" at 14383.5,2138.5 h70
  text "PROJECT TITLE:" at 11343.5,277.5 h45
  text ".PRJ_Title" at 11393.5,144.17 h70
  text "DESIGNED FOR:" at 11343.5,-23.5 h45
  text ".PRJ_Customer" at 11393.5,-163.5 h70
  text "D" at -416.5,-231.5 h70
  text "D" at 14383.5,-231.5 h70
  text "FILE NAME:" at 11343.5,-323.5 h45
  text ".PCB_File_Name_No_Path" at 11393.5,-443.5 h70
  text "Texas Instruments (TI) and/or its licensors do not warrant the accuracy or completeness of this specification" at 6374,-605.34 h45
  text "ENGINEER:" at 11343.5,-613.5 h45
  text "LAYOUT BY:" at 12848.5,-613.5 h45
  text "or any information contained therein. TI and/or its licensors do not warrant that this design will meet" at 6329.01,-718 h45
  text ".PRJ_Engineer" at 11393.5,-768.49 h70
  text ".PCB_Layout" at 12899,-768.49 h70
  text "the specifications, will be suitable for your application or fit for any particular purpose, or will operate in" at 6329.01,-830.67 h45
  text ".Layer_Name" at 577,-858.49 h60
  text "ALTIUM DESIGNER VERSION:" at 12848.5,-923.5 h45
  text "an implementation. TI and/or its licensors do not warrant that the design is production worthy. You should" at 6329.01,-943.33 h45
  text "completely validate and test your design implementation to confirm the system functionality for your application." at 6374,-1056 h45
  text ".print_Scale" at 11393.5,-1056.83 h70
  text ".Application_BuildNumber" at 12899,-1056.83 h70
  text "1" at 739.84,-1263.5 h70
  text "2" at 3235.5,-1263.5 h70
  text "3" at 5724.84,-1263.5 h70
  text "4" at 8231.51,-1263.5 h70
  text "5" at 10730.5,-1263.5 h70
  text "6" at 13235.5,-1263.5 h70
M10 Fab Notes:
  drawing of 173 lines, arcs and shapes, not listed
  text "DESIGN INFORMATION" at 12378.02,6201 h60
  text "MIN. TRACK WIDTH:" at 11733.46,6021 h60
  text "8" at 12829.7,6021 h60
  text "MIL" at 12984.46,6021 h60
  text "MIN. CLEARANCE:" at 11733.46,5889 h60
  text "0.2" at 12769.7,5889 h60
  text "mm" at 12984.46,5889 h60
  text "MIN. VIA PAD SIZE:" at 11733.46,5757 h60
  text "24" at 12799.71,5757 h60
  text "MIL" at 12984.46,5757 h60
  text "0.05mm (2MIL)" at 12428.46,5615.29 h60
  text "MINIMUM ANNULAR RING" at 11404.23,5611 h60
  text "EXTERNAL" at 13136.46,5611 h60
  text "PER" at 11604.23,5493 h60
  text "IPC-D-275 CLASS 2 LEVEL C" at 11824.23,5493 h60
  text "MIL, HOLES" at 13312.46,5380.71 h60
  text "+/-" at 12920,5380 h60
  text "+/-" at 13774,5380 h60
  text "REGISTRATION TOLERANCES:" at 11404.23,5375 h60
  text "METAL" at 12604,5375 h60
  text "5" at 13180.2,5375 h60
  text "3" at 14013.2,5375 h60
  text "MIL" at 14129.46,5375 h60
  text "+/-" at 13774,5262 h60
  text "HOLE SIZE TOLERANCE (UNLESS OTHERWISE SPECIFIED):" at 11404.23,5257 h60
  text "3" at 14013.2,5257 h60
  text "MIL" at 14129.46,5257 h60
  text "MATERIAL:" at 11329.46,5047.54 h60
  text "FR-4 High Tg" at 12315.9,4907.21 h60
  text "FR-408" at 11750.46,4898.64 h60
  text "OTHER" at 13238.46,4898.64 h60
  text "X" at 12161,4895 h60
  text "62 MIL (1.6mm) +/-10%" at 12070.56,4735.92 h60
  text "THICKNESS:" at 11404.23,4731.64 h60
  text "X" at 11942.4,4731.64 h60
  text "OTHER" at 13355.46,4731.64 h60
  text "TOLERANCE:" at 11404.23,4573.64 h60
  text "X" at 12243.53,4573.64 h60
  text "ANSI IPC-6012 TYPE 3 CLASS 2" at 12430.48,4573.64 h60
  text "OTHER +/-" at 12430.46,4417.64 h60
  text "BOW & TWIST:" at 11404.23,4260.64 h60
  text "X" at 12243.53,4260.64 h60
  text "ANSI IPC-6012 TYPE 3 CLASS 2" at 12430.48,4260.64 h60
  text "OTHER +/-" at 12430.46,4102.13 h60
  text "DRILLING:" at 11329.46,3963.64 h60
  text "REFERENCE:" at 11404.23,3846.64 h60
  text "X" at 12052.46,3846.64 h60
  text "AS SHOWN" at 12239.46,3846.64 h60
  text "X" at 12953.46,3846.64 h60
  text "NC_DRILL FILES" at 13090.46,3846.64 h60
  text "PTH COPPER THICKNESS:" at 11404.23,3688.64 h60
  text "X" at 12534.46,3688.64 h60
  text "20-30 um" at 12671.46,3688.64 h60
  text "OTHER" at 13388.46,3688.64 h60
  text "BOARD FINISH:" at 11329.46,3529.64 h60
  text "SILKSCREEN:" at 11484.68,3411.64 h60
  text "X" at 12433.46,3411.64 h60
  text "TOP" at 12559.46,3411.64 h60
  text "X" at 12943.46,3411.64 h60
  text "BOTTOM" at 13070.46,3411.64 h60
  text "SILKSCREEN COLOR:" at 11484.68,3244.64 h60
  text "X" at 12432.42,3244.64 h60
  text "WHITE" at 12559.46,3244.64 h60
  text "OTHER" at 13070.46,3244.64 h60
  text "RED" at 13677.46,3094.44 h60
  text "GREEN" at 12690.46,3085.44 h60
  text "OTHER" at 13308.46,3085.44 h60
  text "X" at 13158,3084 h60
  text "SOLDER RESIST COLOR:" at 11484.68,3074.64 h60
  text "X" at 12563.42,2915.44 h60
  text "MATTE" at 12690.46,2915.44 h60
  text "SEMI-GLOSS" at 13308,2914.8 h60
  text "IMMERSION GOLD (ENIG)" at 12390.46,2726.92 h60
  text "ENEPIG" at 13728,2723.64 h60
  text "SURFACE FINISH:" at 11329.46,2722.64 h60
  text "X" at 12203.51,2722.64 h60
  text "IMM. TIN/SILVER OR EQUIV" at 11659,2565.64 h60
  text "OTHER" at 13090.46,2565.64 h60
  text "ARRAY/PANEL:" at 11329.46,2386.64 h60
  text "CUT AND TRIM PER M1 BOARD OUTLINE" at 12390.46,2382.35 h60
  text "N.C. ROUTE" at 12390.46,2230.64 h60
  text "X" at 13069.46,2230.64 h60
  text "V. SCORE" at 13256.46,2230.64 h60
  text "CERTIFICATION:" at 11329.46,2093.64 h60
  text "MATERIALS AND WORKMANSHIP FOR ALL PCBS" at 12054.46,2093.64 h60
  text "TO MEET OR EXCEED THE REQUIREMENTS OF:" at 12054.46,1995.64 h60
  text "X" at 11680.96,1859.13 h60
  text "ANSI IPC-A-600F CLASS ->" at 11819.96,1859.13 h60
  text "X" at 13459.02,1859.13 h60
  text "2" at 13577.96,1859.14 h60
  text "1" at 13262.96,1857.64 h60
  text "3" at 13931.96,1857.64 h60
  text "X" at 12495.02,1699.64 h60
  text "RoHS" at 12631.96,1699.64 h60
  text "OTHER" at 13276.36,1699.64 h60
  text "PER ORDER" at 13673.42,1699.64 h60
  text "ALL BOARDS MUST MEET OR EXCEED UL94-V0 REQUIREMENTS." at 11357,1534 h60
  text "PCB MUST BEAR THE UL94V-0 UL REGISTERED MATERIAL ID NUMBER" at 11357,1414 h60
  text "ADDITIONAL REQUIREMENTS:" at 11329.46,1240.64 h60
  text "MICROSECTION:" at 11404.23,1125.64 h60
  text "YES" at 12309.96,1125.64 h60
  text "REQUIRED" at 13171.46,969.49 h60
  text "BARE BOARD ELEC. TEST:" at 11404.23,966.64 h60
  text "NONE" at 12709.96,966.64 h60
  text "X" at 13044.46,966.64 h60
  text "PER ORDER" at 13763.46,966.64 h60
  text ".Layer_Name" at 577,-858.49 h60
M11 Gerber Information:
  lines w10: -292,-930.17 6308,-930.17 ; -292,-726.83 6310,-726.83 ; -292,-523.5 -292,-1133.5 3713,-1133.5 6310,-1133.5 6310,-523.5 -291.5,-523.5 -291.5,-1133.5 1284,-1133.5 ; 2173,-1133.5 2173,-523.5 ; 3440,-726.83 3440,-523.5 ; 4280,-726.83 4280,-523.5 ; 4902,-1140 4902,-937.17
  text "ALL ARTWORK VIEWED FROM TOP SIDE" at -228.5,-655.67 h60
  text "BOARD #:" at 2248,-655.67 h60
  text ".PRJ_Number" at 2793.5,-655.67 h60
  text "REV:" at 3638,-655.67 h60
  text ".PCB_Rev" at 3929.5,-655.67 h60
  text "SVN REV:" at 4476,-655.67 h60
  text ".VersionControl_RevNumber" at 4982,-655.67 h60
  text "LAYER NAME =" at -228.5,-858.49 h60
  text "TID #:" at 2248,-859 h60
  text ".TID" at 2793.5,-859 h60
  text "PLOT NAME =" at -228.5,-1064.34 h60
  text ".plot_File_Name" at 577,-1064.34 h60
  text "GENERATED    :" at 2250,-1064.34 h60
  text ".Print_Date" at 3119.5,-1064.34 h60
  text ".Print_Time" at 3848.5,-1064.34 h60
  text "TEXAS INSTRUMENTS" at 5113,-1064.34 h60
M12 Stackup:
  drawing of 295 lines, arcs and shapes, not listed
  text "Layer" at 2660.34,2580 h60
  text "Name" at 3070.26,2580 h60
  text "Material" at 4000,2580 h60
  text "Thickness" at 4859.77,2580 h60
  text "Constant" at 5509.6,2580 h60
  text "Board Layer Stack" at 6079.46,2580 h60
  text "Top Overlay" at 3070.26,2460 h60
  text "Top Solder" at 3070.26,2340 h60
  text "Solder Resist" at 4000,2340 h60
  text "0.40mil" at 4859.77,2340 h60
  text "3.5" at 5509.6,2340 h60
  text "1" at 2660.34,2220 h60
  text "Top Layer" at 3070.26,2220 h60
  text "1.40mil" at 4859.77,2220 h60
  text "Dielectric1" at 3070.26,2100 h60
  text "FR-4" at 4000,2100 h60
  text "8.00mil" at 4859.77,2100 h60
  text "4.2" at 5509.6,2100 h60
  text "2" at 2660.34,1980 h60
  text "GND" at 3070.26,1980 h60
  text "1.40mil" at 4859.77,1980 h60
  text "Dielectric 2" at 3070.26,1860 h60
  text "FR-4" at 4000,1860 h60
  text "40.00mil" at 4859.77,1860 h60
  text "4.2" at 5509.6,1860 h60
  text "3" at 2660.34,1740 h60
  text "Power" at 3070.26,1740 h60
  text "1.40mil" at 4859.77,1740 h60
  text "Dielectric 3" at 3070.26,1620 h60
  text "FR-4" at 4000,1620 h60
  text "8.00mil" at 4859.77,1620 h60
  text "4.2" at 5509.6,1620 h60
  text "4" at 2660.34,1500 h60
  text "Bottom Layer" at 3070.26,1500 h60
  text "1.40mil" at 4859.77,1500 h60
  text "Bottom Solder" at 3070.26,1380 h60
  text "Solder Resist" at 4000,1380 h60
  text "0.40mil" at 4859.77,1380 h60
  text "3.5" at 5509.6,1380 h60
  text "Bottom Overlay" at 3070.26,1260 h60
  text ".Layer_Name" at 577,-858.49 h60
M13 Component Bodies Top:
  text ".Layer_Name" at 577,-858.49 h60
M14 Component Bodies Bottom:
  text ".Layer_Name" at 577,-858.49 h60
M15 Courtyards Top:
  text ".Layer_Name" at 577,-858.49 h60
M16 Courtyards Bottom:
  text ".Layer_Name" at 577,-858.49 h60
Drill Drawing:
  circle w10: c2646.97,690.59 r27.67
  lines w10: 2619.3,178.75 2633.13,178.75 2633.13,164.92 2660.8,164.92 2660.8,178.75 2674.63,178.75 2674.63,206.42 2660.8,206.42 2660.8,220.25 2633.13,220.25 2633.13,206.42 2619.3,206.42 2619.3,178.75 ; 2619.3,303.25 2633.13,303.25 2646.97,289.42 2660.8,303.25 2674.63,303.25 2660.8,317.09 2674.63,330.92 2660.8,330.92 2646.97,344.75 2633.13,330.92 2619.3,330.92 2633.13,317.09 2619.3,303.25 ; 2619.3,413.92 2674.63,413.92 2674.63,469.25 2619.3,469.25 2619.3,413.92 ; 2619.3,538.42 2646.97,552.25 2674.63,538.42 2660.8,566.09 2674.63,593.75 2646.97,579.92 2619.3,593.75 2633.13,566.09 2619.3,538.42 ; 2619.3,815.09 2646.97,787.42 2674.63,815.09 2646.97,842.75 2619.3,815.09
  lines w12: 2569.14,127.57 5801.33,127.57 ; 2569.14,874.57 5801.33,874.57 ; 2907.15,3.07 2907.15,999.07 ; 3239.31,3.07 3239.31,999.07 ; 3875.79,3.07 3875.79,999.07 ; 4134.99,3.07 4134.99,999.07 ; 4510.23,3.07 4510.23,999.07 ; 5234.78,3.07 5234.78,999.07 ; 2569.14,3.07 5801.33,3.07 5801.33,999.07 2569.14,999.07 2569.14,3.07
  text "Symbol" at 2643.84,911.92 h72
  text "Quantity" at 2944.5,911.92 h72
  text "Finished Hole Size" at 3276.66,911.92 h72
  text "Plated" at 3913.14,911.92 h72
  text "Hole Type" at 4172.34,911.92 h72
  text "Drill Layer Pair" at 4547.58,911.92 h72
  text "Hole Tolerance" at 5272.13,911.92 h72
  text "2" at 2944.5,787.42 h60
  text "7.87mil (0.200mm)" at 3276.66,787.42 h60
  text "PTH" at 3913.14,787.42 h60
  text "Round" at 4172.34,787.42 h60
  text "Top Layer - Bottom Layer" at 4547.58,787.42 h60
  text "184" at 2944.5,662.92 h60
  text "16.00mil (0.406mm)" at 3276.66,662.92 h60
  text "PTH" at 3913.14,662.92 h60
  text "Round" at 4172.34,662.92 h60
  text "Top Layer - Bottom Layer" at 4547.58,662.92 h60
  text "6" at 2944.5,538.42 h60
  text "40.00mil (1.016mm)" at 3276.66,538.42 h60
  text "PTH" at 3913.14,538.42 h60
  text "Round" at 4172.34,538.42 h60
  text "Top Layer - Bottom Layer" at 4547.58,538.42 h60
  text "40" at 2944.5,413.92 h60
  text "40.16mil (1.020mm)" at 3276.66,413.92 h60
  text "PTH" at 3913.14,413.92 h60
  text "Round" at 4172.34,413.92 h60
  text "Top Layer - Bottom Layer" at 4547.58,413.92 h60
  text "8" at 2944.5,289.42 h60
  text "51.18mil (1.300mm)" at 3276.66,289.42 h60
  text "PTH" at 3913.14,289.42 h60
  text "Round" at 4172.34,289.42 h60
  text "Top Layer - Bottom Layer" at 4547.58,289.42 h60
  text "16" at 2944.5,164.92 h60
  text "62.99mil (1.600mm)" at 3276.66,164.92 h60
  text "PTH" at 3913.14,164.92 h60
  text "Round" at 4172.34,164.92 h60
  text "Top Layer - Bottom Layer" at 4547.58,164.92 h60
  text "256 Total" at 2944.5,40.42 h60
  text ".Layer_Name" at 577,-858.49 h60
M17 Embedded Cavity:
  text ".Layer_Name" at 577,-858.49 h60
M18 Embedded Assembly:
  text ".Layer_Name" at 577,-858.49 h60
M19 Embedded Keepout:
  text ".Layer_Name" at 577,-858.49 h60

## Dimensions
0,-400 to 1000,-400 on M2 Board Dimensions
0,0 to 0,3346.46 on M2 Board Dimensions
0,0 to 2362.2,0 on M2 Board Dimensions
